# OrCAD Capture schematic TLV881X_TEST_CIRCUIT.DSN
size A; title: TLV8811/8812 425nA Precision Nanopower Op Amps; rev: 1.0; company: Texas Instruments Inc., Tucson, AZ; note: Datasheet: SNOSD35A          EVM: N/A; note: 251 S Williams Blvd; note: Tucson, AZ, 85711
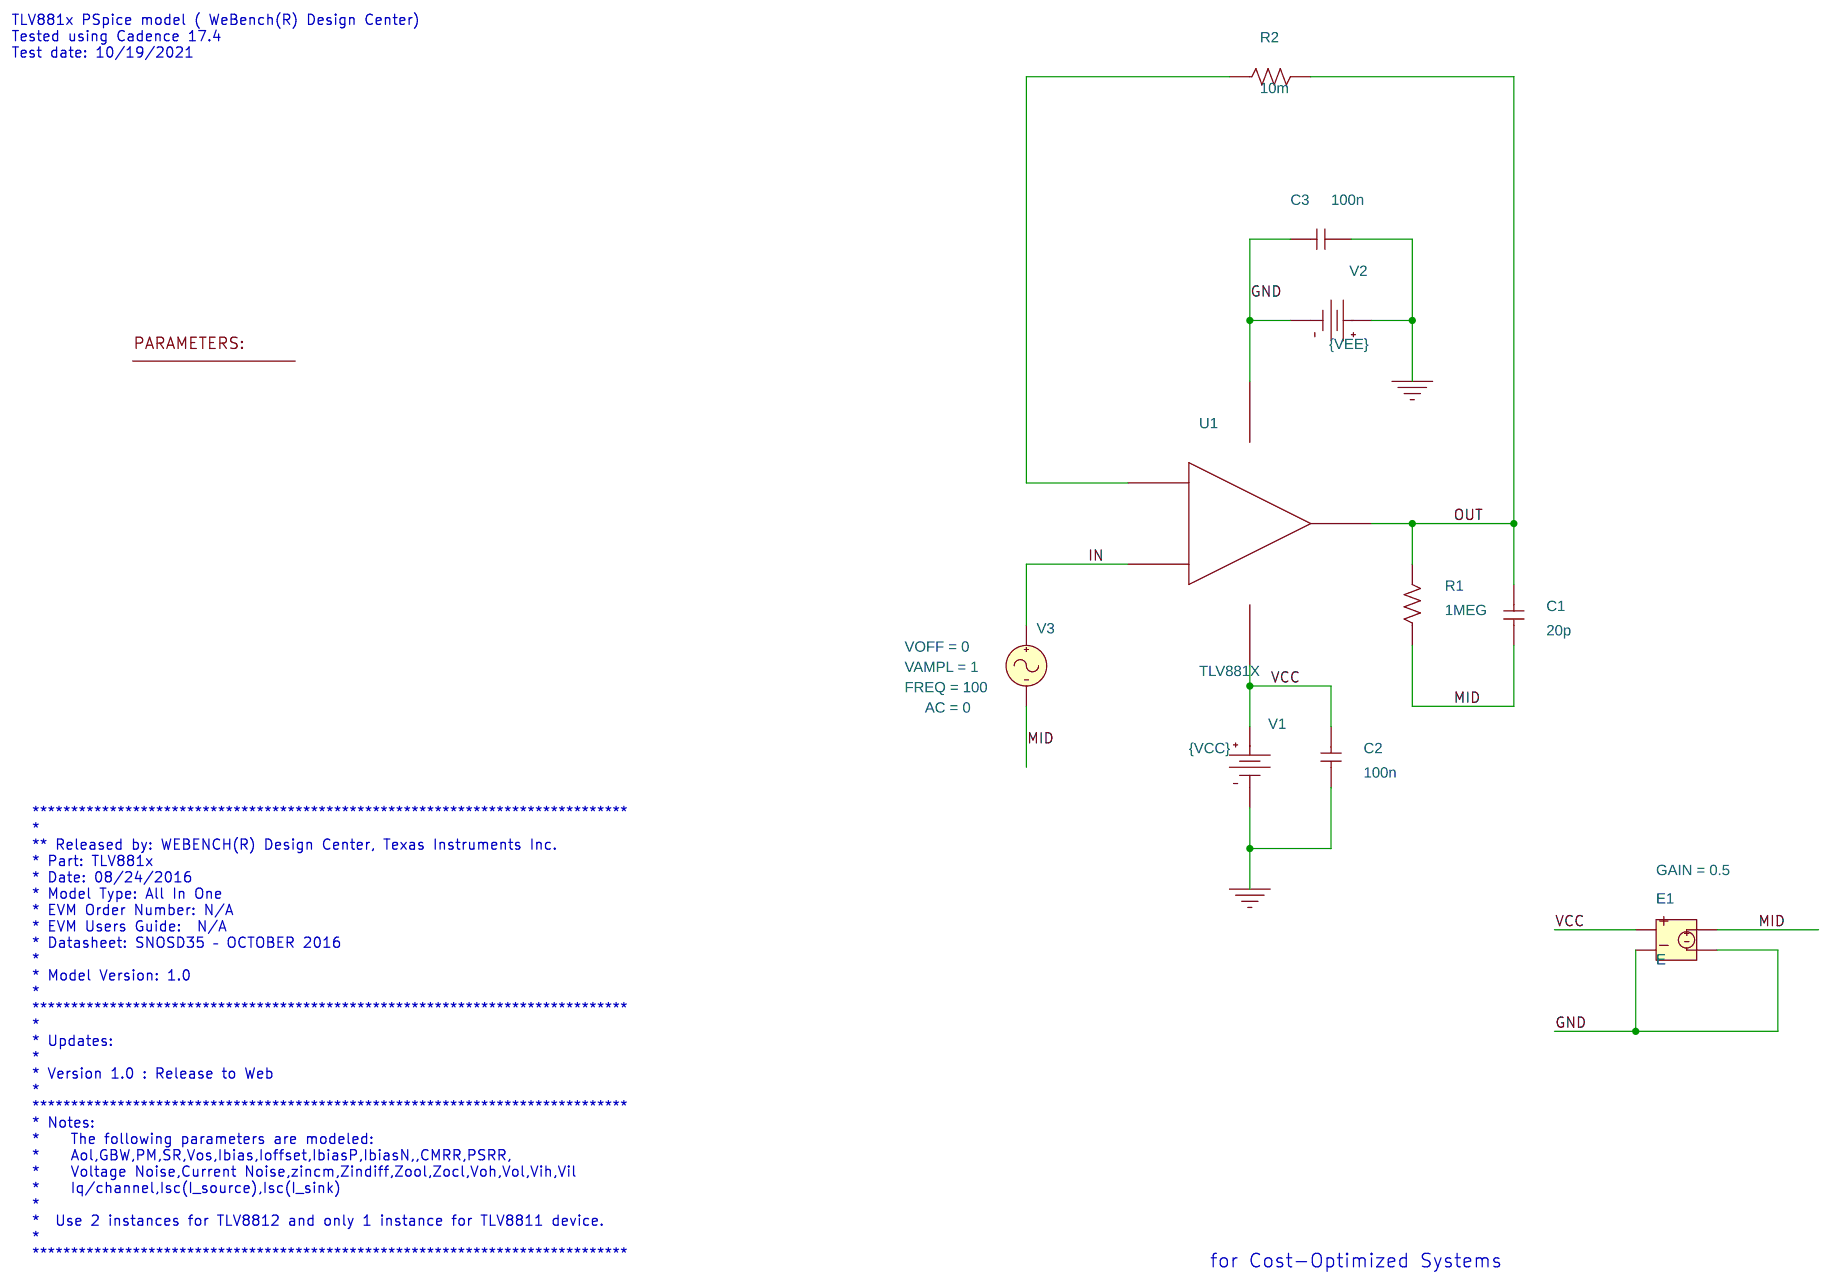
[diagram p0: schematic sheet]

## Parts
1  PARAM
C1  20p  [cap196]
C2  100n  [cap196]
C3  100n  [cap196]
E1  E
R1  1MEG  [AXRC05]
R2  10m  [AXRC05]
U1  TLV881X
V1  VDC
V2  VDC
V3  VSIN

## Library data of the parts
1 = PARAM: VCC: 5; VEE: 0
C1-C3 = C
E1 = E: GAIN: 0.5
R1 R2 = R
U1 = TLV881X
V1 = VDC: DC: {VCC}
V2 = VDC: DC: {VEE}
V3 = VSIN: AC: 0; AppProp: Sine$Voltage$0$-1; DC: 0; FREQ: 100; TD: 10u; VAMPL: 1; VOFF: 0

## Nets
GND: C3.2 E1.2 E1.4 U1.V- V2.1(-)
VCC: C2.2 E1.1 U1.V+ V1.0(+)
0: C2.1 C3.1 V1.1(-) V2.0(+)
IN: U1.+IN V3.1(+)
MID: C1.1 E1.3 R1.1 V3.2(-)
OUT: C1.2 R1.2 R2.2 U1.OUT
N00171: R2.1 U1.-IN

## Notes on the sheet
- TLV881x PSpice model ( WeBench(R) Design Center)
  Tested using Cadence 17.4
  Test date: 10/19/2021
- *****************************************************************************
  *
  ** Released by: WEBENCH(R) Design Center, Texas Instruments Inc.
  * Part: TLV881x
  * Date: 08/24/2016
  * Model Type: All In One
  * EVM Order Number: N/A
  * EVM Users Guide:  N/A
  * Datasheet: SNOSD35 – OCTOBER 2016
  *
  * Model Version: 1.0
  *
  *****************************************************************************
  *
  * Updates:
  *
  * Version 1.0 : Release to Web
  *
  *****************************************************************************
  * Notes:
  *    The following parameters are modeled:
  *    Aol,GBW,PM,SR,Vos,Ibias,Ioffset,IbiasP,IbiasN,,CMRR,PSRR,
  *    Voltage Noise,Current Noise,zincm,Zindiff,Zool,Zocl,Voh,Vol,Vih,Vil
  *    Iq/channel,Isc(I_source),Isc(I_sink)
  *
  *  Use 2 instances for TLV8812 and only 1 instance for TLV8811 device.
  *
  *****************************************************************************
- for Cost-Optimized Systems
